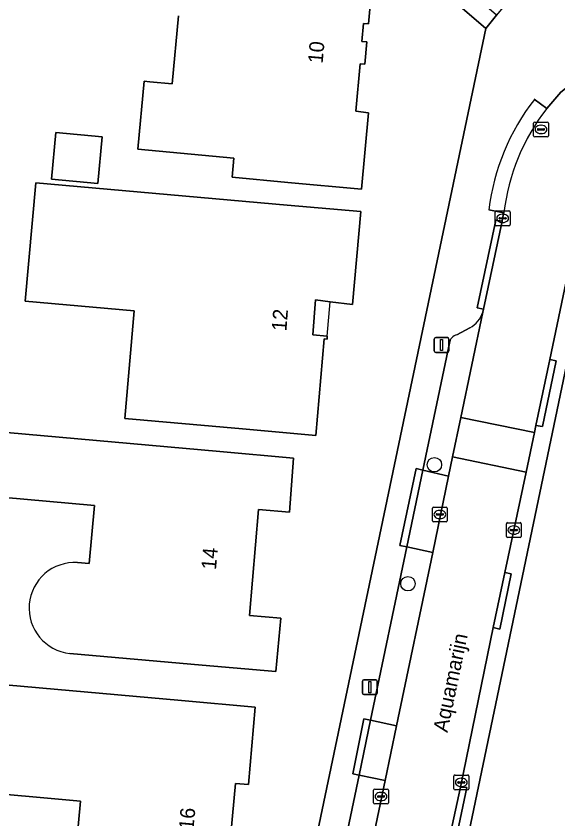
# Model space of a CAD drawing. Extents: x 159626 to 160723, y 388173 to 389416.
# Drawn here: x 159871.8 to 159908.4, y 388559.2 to 388613.5 of the extents above; entities that cross this region are included whole.
import ezdxf

# ---------------------------------------------------------------- set-up
doc = ezdxf.new("R2010")
doc.units = 0
for name, color, linetype in [('IMGEO_Boom', 7, 'Continuous'), ('IMGEO_Erf', 7, 'Continuous'), ('IMGEO_Groenvoorziening', 7, 'Continuous'), ('IMGEO_Kolk', 7, 'Continuous'), ('IMGEO_Lichtmast', 7, 'Continuous'), ('IMGEO_Openbare_ruimte_label', 7, 'Continuous'), ('IMGEO_Pand', 7, 'Continuous'), ('IMGEO_Pand_nummerreeks', 7, 'Continuous'), ('IMGEO_Pand_overbouw', 7, 'Continuous'), ('IMGEO_Parkeervlak_open', 7, 'Continuous'), ('IMGEO_Rijbaan_lokaal_open', 7, 'Continuous'), ('IMGEO_Rioolput', 7, 'Continuous'), ('IMGEO_Voetpad_open', 7, 'Continuous')]:
    doc.layers.add(name, color=color, linetype=linetype)

msp = doc.modelspace()

# ---------------------------------------------------------------- linework, layer by layer
at = {"layer": 'IMGEO_Boom'}
for centre in [(159900.068, 388583.165), (159898.281, 388575.119)]:
    msp.add_circle(centre, 0.489, dxfattribs=at)
at = {"layer": 'IMGEO_Erf'}
for points in [[(159903.537, 388612.665), (159870.877, 388640.759), (159868.257, 388629.83), (159864.584, 388613.795), (159856.856, 388575.073), (159855.899, 388569.574), (159854.79, 388569.739), (159851.654, 388551.438)], [(159895.744, 388614.471), (159895.614, 388612.976), (159895.275, 388613.005), (159895.17, 388611.79), (159895.509, 388611.761), (159895.358, 388610.258), (159895.038, 388610.285), (159894.759, 388607.067), (159895.621, 388606.967), (159895.129, 388601.801), (159890.151, 388602.262), (159886.384, 388602.611), (159886.504, 388603.907), (159880.021, 388604.507), (159880.446, 388609.095), (159880.817, 388609.061), (159882.341, 388608.919), (159882.767, 388613.527)], [(159880.922, 388504.632), (159903.537, 388612.665)], [(159910.917, 388599.067), (159890.615, 388501.836)], [(159875.928, 388576.55), (159876.729, 388576.48), (159877.072, 388580.416), (159870.779, 388580.965), (159870.808, 388581.302), (159864.354, 388581.864), (159864.694, 388585.766), (159871.148, 388585.204), (159871.16, 388585.34), (159885.557, 388584.052), (159890.537, 388583.606), (159890.274, 388579.96), (159888.18, 388580.138), (159887.557, 388572.968), (159889.688, 388572.787), (159889.353, 388569.19), (159884.372, 388569.624), (159875.415, 388570.404)]]:
    msp.add_lwpolyline(points, dxfattribs=at)
for points in [[(159874.169, 388602.469), (159874.461, 388605.625), (159877.59, 388605.335), (159877.297, 388602.179)], [(159872.4, 388594.22), (159873.11, 388602.22), (159890.121, 388600.728), (159895.101, 388600.291), (159894.524, 388594.006), (159893.019, 388594.19), (159892.036, 388594.311), (159891.838, 388591.95), (159892.824, 388591.867), (159892.807, 388591.667), (159892.605, 388591.683), (159892.059, 388585.15), (159887.079, 388585.59), (159879.122, 388586.294), (159879.765, 388593.569)], [(159868.39, 388561.11), (159868.882, 388566.952), (159868.194, 388567.009), (159867.157, 388566.197), (159865.365, 388566.357), (159865.581, 388568.776), (159869.01, 388568.47), (159882.96, 388567.225), (159887.94, 388566.78), (159887.496, 388561.533), (159886.609, 388561.603), (159885.79, 388552.622), (159882.972, 388552.878), (159882.862, 388551.663), (159877.883, 388552.116), (159875.394, 388552.342), (159876.127, 388560.407)]]:
    msp.add_lwpolyline(points, close=True, dxfattribs=at)
msp.add_arc((159875.745, 388573.471), 3.085, 86.5972, 263.8601, dxfattribs=at)
at = {"layer": 'IMGEO_Groenvoorziening'}
msp.add_lwpolyline([(159855.899, 388569.574), (159856.856, 388575.073), (159864.584, 388613.795), (159868.257, 388629.83), (159870.877, 388640.759), (159903.537, 388612.665), (159904.269, 388613.569), (159871.151, 388642.007), (159870.675, 388642.416), (159870.33, 388642.677), (159870.008, 388642.843), (159865.23, 388644.686), (159864.406, 388645.004), (159862.861, 388640.687), (159864.137, 388640.247), (159866.102, 388639.571), (159861.174, 388619.427), (159856.533, 388594.848)], dxfattribs=at)
at = {"layer": 'IMGEO_Kolk'}
for p, q in [((159904.181, 388599.4), (159904.181, 388600.252)), ((159904.256, 388600.326), (159905.108, 388600.326)), ((159904.669, 388600.106), (159904.694, 388600.106)), ((159905.182, 388600.252), (159905.182, 388599.4)), ((159904.44, 388599.82), (159904.44, 388599.832)), ((159904.878, 388599.783), (159904.48, 388599.783)), ((159904.483, 388599.869), (159904.881, 388599.869)), ((159904.692, 388599.546), (159904.667, 388599.546)), ((159904.924, 388599.832), (159904.924, 388599.82)), ((159905.108, 388599.326), (159904.256, 388599.326)), ((159899.938, 388579.376), (159899.938, 388580.228)), ((159900.013, 388580.302), (159900.865, 388580.302)), ((159900.426, 388580.082), (159900.451, 388580.082)), ((159900.939, 388580.228), (159900.939, 388579.376)), ((159900.197, 388579.796), (159900.197, 388579.808)), ((159900.635, 388579.759), (159900.237, 388579.759)), ((159900.24, 388579.845), (159900.638, 388579.845)), ((159900.449, 388579.522), (159900.424, 388579.522)), ((159900.681, 388579.808), (159900.681, 388579.796)), ((159900.865, 388579.302), (159900.013, 388579.302)), ((159904.942, 388578.323), (159904.942, 388579.175)), ((159905.017, 388579.249), (159905.869, 388579.249)), ((159905.43, 388579.029), (159905.455, 388579.029)), ((159905.943, 388579.175), (159905.943, 388578.323)), ((159905.201, 388578.743), (159905.201, 388578.755)), ((159905.639, 388578.706), (159905.241, 388578.706)), ((159905.244, 388578.792), (159905.642, 388578.792)), ((159905.453, 388578.469), (159905.428, 388578.469)), ((159905.685, 388578.755), (159905.685, 388578.743)), ((159905.869, 388578.249), (159905.017, 388578.249)), ((159901.388, 388561.26), (159901.388, 388562.112)), ((159901.463, 388562.186), (159902.315, 388562.186)), ((159902.389, 388562.112), (159902.389, 388561.26)), ((159901.647, 388561.68), (159901.647, 388561.692)), ((159902.085, 388561.643), (159901.687, 388561.643)), ((159901.69, 388561.729), (159902.088, 388561.729)), ((159901.876, 388561.966), (159901.901, 388561.966)), ((159902.131, 388561.692), (159902.131, 388561.68)), ((159895.955, 388560.307), (159895.955, 388561.159)), ((159896.03, 388561.233), (159896.882, 388561.233)), ((159896.443, 388561.013), (159896.468, 388561.013)), ((159896.956, 388561.159), (159896.956, 388560.307)), ((159902.315, 388561.186), (159901.463, 388561.186)), ((159901.899, 388561.406), (159901.874, 388561.406)), ((159896.214, 388560.727), (159896.214, 388560.739)), ((159896.652, 388560.69), (159896.254, 388560.69)), ((159896.257, 388560.776), (159896.655, 388560.776)), ((159896.466, 388560.453), (159896.441, 388560.453)), ((159896.698, 388560.739), (159896.698, 388560.727)), ((159896.882, 388560.233), (159896.03, 388560.233))]:
    msp.add_line(p, q, dxfattribs=at)
for points in [[(159904.181, 388599.4), (159904.181, 388600.252)], [(159904.256, 388600.326), (159905.108, 388600.326)], [(159905.182, 388600.252), (159905.182, 388599.4)], [(159905.108, 388599.326), (159904.256, 388599.326)], [(159899.938, 388579.376), (159899.938, 388580.228)], [(159900.013, 388580.302), (159900.865, 388580.302)], [(159900.939, 388580.228), (159900.939, 388579.376)], [(159900.865, 388579.302), (159900.013, 388579.302)], [(159904.942, 388578.323), (159904.942, 388579.175)], [(159905.017, 388579.249), (159905.869, 388579.249)], [(159905.943, 388579.175), (159905.943, 388578.323)], [(159905.869, 388578.249), (159905.017, 388578.249)], [(159901.388, 388561.26), (159901.388, 388562.112)], [(159901.463, 388562.186), (159902.315, 388562.186)], [(159902.389, 388562.112), (159902.389, 388561.26)], [(159895.955, 388560.307), (159895.955, 388561.159)], [(159896.03, 388561.233), (159896.882, 388561.233)], [(159896.956, 388561.159), (159896.956, 388560.307)], [(159902.315, 388561.186), (159901.463, 388561.186)], [(159896.882, 388560.233), (159896.03, 388560.233)]]:
    msp.add_lwpolyline(points, dxfattribs=at)
for centre, radius, start, end in [((159904.258, 388600.25), 0.0765, 91.552, 178.448), ((159904.258, 388600.25), 0.0765, 91.552, 178.448), ((159905.106, 388600.25), 0.0765, 1.552, 88.448), ((159905.106, 388600.25), 0.0765, 1.552, 88.448), ((159904.48, 388599.829), 0.0403, 85.8775, 175.7526), ((159904.477, 388599.819), 0.0366, 178.938, 274.7102), ((159904.881, 388599.826), 0.043, 264.8664, 352.4533), ((159904.885, 388599.831), 0.0386, 1.7309, 96.639), ((159904.258, 388599.402), 0.0765, 181.552, 268.448), ((159904.258, 388599.402), 0.0765, 181.552, 268.448), ((159905.106, 388599.402), 0.0765, 271.552, 358.448), ((159905.106, 388599.402), 0.0765, 271.552, 358.448), ((159900.015, 388580.226), 0.0765, 91.552, 178.448), ((159900.015, 388580.226), 0.0765, 91.552, 178.448), ((159900.863, 388580.226), 0.0765, 1.552, 88.448), ((159900.863, 388580.226), 0.0765, 1.552, 88.448), ((159900.015, 388579.378), 0.0765, 181.552, 268.448), ((159900.015, 388579.378), 0.0765, 181.552, 268.448), ((159900.237, 388579.805), 0.0403, 85.8775, 175.7526), ((159900.234, 388579.795), 0.0366, 178.938, 274.7102), ((159900.638, 388579.802), 0.043, 264.8664, 352.4533), ((159900.642, 388579.807), 0.0386, 1.7309, 96.639), ((159900.863, 388579.378), 0.0765, 271.552, 358.448), ((159900.863, 388579.378), 0.0765, 271.552, 358.448), ((159905.019, 388579.173), 0.0765, 91.552, 178.448), ((159905.019, 388579.173), 0.0765, 91.552, 178.448), ((159905.867, 388579.173), 0.0765, 1.552, 88.448), ((159905.867, 388579.173), 0.0765, 1.552, 88.448), ((159905.019, 388578.325), 0.0765, 181.552, 268.448), ((159905.019, 388578.325), 0.0765, 181.552, 268.448), ((159905.241, 388578.752), 0.0403, 85.8775, 175.7526), ((159905.238, 388578.742), 0.0366, 178.938, 274.7102), ((159905.642, 388578.749), 0.043, 264.8664, 352.4533), ((159905.646, 388578.754), 0.0386, 1.7309, 96.639), ((159905.867, 388578.325), 0.0765, 271.552, 358.448), ((159905.867, 388578.325), 0.0765, 271.552, 358.448), ((159901.465, 388562.11), 0.0765, 91.552, 178.448), ((159901.465, 388562.11), 0.0765, 91.552, 178.448), ((159902.313, 388562.11), 0.0765, 1.552, 88.448), ((159902.313, 388562.11), 0.0765, 1.552, 88.448), ((159901.687, 388561.689), 0.0403, 85.8775, 175.7526), ((159901.684, 388561.679), 0.0366, 178.938, 274.7102), ((159902.088, 388561.686), 0.043, 264.8664, 352.4533), ((159902.092, 388561.691), 0.0386, 1.7309, 96.639), ((159896.032, 388561.157), 0.0765, 91.552, 178.448), ((159896.032, 388561.157), 0.0765, 91.552, 178.448), ((159896.88, 388561.157), 0.0765, 1.552, 88.448), ((159896.88, 388561.157), 0.0765, 1.552, 88.448), ((159901.465, 388561.262), 0.0765, 181.552, 268.448), ((159901.465, 388561.262), 0.0765, 181.552, 268.448), ((159902.313, 388561.262), 0.0765, 271.552, 358.448), ((159902.313, 388561.262), 0.0765, 271.552, 358.448), ((159896.254, 388560.736), 0.0403, 85.8775, 175.7526), ((159896.251, 388560.726), 0.0366, 178.938, 274.7102), ((159896.655, 388560.733), 0.043, 264.8664, 352.4533), ((159896.659, 388560.738), 0.0386, 1.7309, 96.639), ((159896.032, 388560.309), 0.0765, 181.552, 268.448), ((159896.032, 388560.309), 0.0765, 181.552, 268.448), ((159896.88, 388560.309), 0.0765, 271.552, 358.448), ((159896.88, 388560.309), 0.0765, 271.552, 358.448)]:
    msp.add_arc(centre, radius, start, end, dxfattribs=at)
for centre, major_axis, ratio, start_param, end_param in [((159904.668, 388599.826), (-0.387, 0.002), 0.722429, 4.712389, 7.853982), ((159904.693, 388599.826), (-0.39, 0.002), 0.717154, 1.570796, 4.712389), ((159900.425, 388579.802), (-0.387, 0.002), 0.722429, 4.712389, 7.853982), ((159900.45, 388579.802), (-0.39, 0.002), 0.717154, 1.570796, 4.712389), ((159905.429, 388578.749), (-0.387, 0.002), 0.722429, 4.712389, 7.853982), ((159905.454, 388578.749), (-0.39, 0.002), 0.717154, 1.570796, 4.712389), ((159901.875, 388561.686), (-0.387, 0.002), 0.722429, 4.712389, 7.853982), ((159901.9, 388561.686), (-0.39, 0.002), 0.717154, 1.570796, 4.712389), ((159896.442, 388560.733), (-0.387, 0.002), 0.722429, 4.712389, 7.853982), ((159896.467, 388560.733), (-0.39, 0.002), 0.717154, 1.570796, 4.712389)]:
    msp.add_ellipse(centre, major_axis=major_axis, ratio=ratio, start_param=start_param, end_param=end_param, dxfattribs=at)
at = {"layer": 'IMGEO_Lichtmast'}
for p, q in [((159900.054, 388590.864), (159900.054, 388591.664)), ((159900.054, 388591.664), (159900.054, 388590.864)), ((159900.154, 388591.764), (159900.944, 388591.764)), ((159900.944, 388591.764), (159900.154, 388591.764)), ((159901.044, 388591.664), (159901.044, 388590.864)), ((159901.044, 388590.864), (159901.044, 388591.664)), ((159900.944, 388590.764), (159900.154, 388590.764)), ((159900.154, 388590.764), (159900.944, 388590.764)), ((159895.206, 388567.725), (159895.206, 388568.525)), ((159895.206, 388568.525), (159895.206, 388567.725)), ((159895.306, 388568.625), (159896.096, 388568.625)), ((159896.096, 388568.625), (159895.306, 388568.625)), ((159896.196, 388568.525), (159896.196, 388567.725)), ((159896.196, 388567.725), (159896.196, 388568.525)), ((159896.096, 388567.625), (159895.306, 388567.625)), ((159895.306, 388567.625), (159896.096, 388567.625))]:
    msp.add_line(p, q, dxfattribs=at)
for points in [[(159900.474, 388591.639), (159900.624, 388591.639), (159900.624, 388590.889), (159900.474, 388590.889), (159900.474, 388591.639)], [(159895.626, 388568.5), (159895.776, 388568.5), (159895.776, 388567.75), (159895.626, 388567.75), (159895.626, 388568.5)]]:
    msp.add_lwpolyline(points, dxfattribs=at)
for centre, start, end in [((159900.154, 388591.664), 90, 180), ((159900.154, 388591.664), 90, 180), ((159900.944, 388591.664), 0, 90), ((159900.944, 388591.664), 360, 90), ((159900.154, 388590.864), 180, 270), ((159900.154, 388590.864), 180, 270), ((159900.944, 388590.864), 270, 0), ((159900.944, 388590.864), 270, 0), ((159895.306, 388568.525), 90, 180), ((159895.306, 388568.525), 90, 180), ((159896.096, 388568.525), 0, 90), ((159896.096, 388568.525), 360, 90), ((159895.306, 388567.725), 180, 270), ((159895.306, 388567.725), 180, 270), ((159896.096, 388567.725), 270, 0), ((159896.096, 388567.725), 270, 0)]:
    msp.add_arc(centre, 0.1, start, end, dxfattribs=at)
at = {"layer": 'IMGEO_Pand'}
for points in [[(159882.767, 388613.527), (159882.341, 388608.919), (159880.817, 388609.061), (159880.446, 388609.095), (159880.021, 388604.507), (159886.504, 388603.907), (159886.384, 388602.611), (159890.151, 388602.262), (159895.129, 388601.801), (159895.621, 388606.967), (159894.759, 388607.067), (159895.038, 388610.285), (159895.358, 388610.258), (159895.509, 388611.761), (159895.17, 388611.79), (159895.275, 388613.005), (159895.614, 388612.976), (159895.744, 388614.471)], [(159888.18, 388580.138), (159890.274, 388579.96), (159890.537, 388583.606), (159885.557, 388584.052), (159871.16, 388585.34), (159871.148, 388585.204), (159870.808, 388581.302), (159870.779, 388580.965), (159877.072, 388580.416), (159876.729, 388576.48), (159875.928, 388576.55)], [(159875.415, 388570.404), (159884.372, 388569.624), (159889.353, 388569.19), (159889.688, 388572.787), (159887.557, 388572.968), (159888.18, 388580.138)]]:
    msp.add_lwpolyline(points, dxfattribs=at)
for points in [[(159877.59, 388605.335), (159874.461, 388605.625), (159874.169, 388602.469), (159877.297, 388602.179)], [(159893.019, 388594.19), (159894.524, 388594.006), (159895.101, 388600.291), (159890.121, 388600.728), (159873.11, 388602.22), (159872.4, 388594.22), (159879.765, 388593.569), (159879.122, 388586.294), (159887.079, 388585.59), (159892.059, 388585.15), (159892.605, 388591.683), (159892.807, 388591.667), (159892.824, 388591.867), (159891.838, 388591.95), (159892.036, 388594.311)], [(159869.01, 388568.47), (159865.581, 388568.776), (159865.365, 388566.357), (159867.157, 388566.197), (159868.194, 388567.009), (159868.882, 388566.952), (159868.39, 388561.11), (159876.127, 388560.407), (159875.394, 388552.342), (159877.883, 388552.116), (159882.862, 388551.663), (159882.972, 388552.878), (159885.79, 388552.622), (159886.609, 388561.603), (159887.496, 388561.533), (159887.94, 388566.78), (159882.96, 388567.225)]]:
    msp.add_lwpolyline(points, close=True, dxfattribs=at)
msp.add_arc((159875.745, 388573.471), 3.085, 86.5972, 263.8601, dxfattribs=at)
at = {"layer": 'IMGEO_Pand_overbouw'}
msp.add_lwpolyline([(159893.019, 388594.19), (159892.036, 388594.311), (159891.838, 388591.95), (159892.824, 388591.867)], close=True, dxfattribs=at)
at = {"layer": 'IMGEO_Parkeervlak_open'}
for points in [[(159901.09, 388591.384), (159899.283, 388582.799), (159901.032, 388582.402), (159901.302, 388583.693), (159901.859, 388586.36), (159903.349, 388593.491)], [(159902.475, 388592.429), (159901.594, 388591.959)]]:
    msp.add_lwpolyline(points, dxfattribs=at)
for points in [[(159901.032, 388582.402), (159899.283, 388582.799), (159898.198, 388577.61), (159899.954, 388577.243)], [(159899.954, 388577.243), (159898.198, 388577.61), (159895.745, 388565.885), (159897.504, 388565.517)], [(159897.504, 388565.517), (159895.745, 388565.885), (159894.97, 388562.181), (159896.73, 388561.813)], [(159896.73, 388561.813), (159894.97, 388562.181), (159889.959, 388538.221), (159891.723, 388537.852)]]:
    msp.add_lwpolyline(points, close=True, dxfattribs=at)
for centre, radius, start, end in [((159901.541, 388594.088), 1.904, 299.3707, 341.7222), ((159901.724, 388591.337), 0.635, 101.7721, 175.7573)]:
    msp.add_arc(centre, radius, start, end, dxfattribs=at)
at = {"layer": 'IMGEO_Rijbaan_lokaal_open'}
for points in [[(159913.358, 388605.815), (159914.07, 388606.423), (159932.598, 388621.187), (159933.737, 388622.071), (159930.674, 388625.944), (159929.504, 388625.028), (159924.843, 388621.328), (159908.628, 388608.359), (159907.664, 388607.259)], [(159904.765, 388600.195), (159904.679, 388599.826), (159904.661, 388599.629), (159903.389, 388593.676), (159903.349, 388593.491), (159901.859, 388586.36), (159906.837, 388585.341), (159906.939, 388585.824), (159907.864, 388590.284), (159909.761, 388599.318)]]:
    msp.add_lwpolyline(points, dxfattribs=at)
for points in [[(159901.859, 388586.36), (159901.302, 388583.693), (159906.268, 388582.656), (159906.837, 388585.341)], [(159900.706, 388556.171), (159901.827, 388561.363), (159904.043, 388572.152), (159904.831, 388575.878), (159906.268, 388582.656), (159901.302, 388583.693), (159901.032, 388582.402), (159899.954, 388577.243), (159897.504, 388565.517), (159896.73, 388561.813), (159891.723, 388537.852), (159891.115, 388534.944), (159890.558, 388532.274), (159889.31, 388526.304), (159887.996, 388520.015), (159892.92, 388519.028), (159894.104, 388524.658), (159895.037, 388529.114), (159897.401, 388540.306), (159898.454, 388545.528)]]:
    msp.add_lwpolyline(points, close=True, dxfattribs=at)
msp.add_arc((159918.924, 388598.511), 14.259, 142.1568, 173.2176, dxfattribs=at)
at = {"layer": 'IMGEO_Rioolput'}
for p, q in [((159906.777, 388605.414), (159906.777, 388606.266)), ((159906.852, 388606.34), (159907.704, 388606.34)), ((159907.265, 388606.12), (159907.29, 388606.12)), ((159907.778, 388606.266), (159907.778, 388605.414)), ((159907.036, 388605.834), (159907.036, 388605.846)), ((159907.474, 388605.797), (159907.076, 388605.797)), ((159907.079, 388605.883), (159907.477, 388605.883)), ((159907.288, 388605.56), (159907.263, 388605.56)), ((159907.52, 388605.846), (159907.52, 388605.834)), ((159907.704, 388605.34), (159906.852, 388605.34))]:
    msp.add_line(p, q, dxfattribs=at)
for points in [[(159906.777, 388605.414), (159906.777, 388606.266)], [(159906.852, 388606.34), (159907.704, 388606.34)], [(159907.778, 388606.266), (159907.778, 388605.414)], [(159907.704, 388605.34), (159906.852, 388605.34)]]:
    msp.add_lwpolyline(points, dxfattribs=at)
for centre, radius, start, end in [((159906.854, 388606.264), 0.0765, 91.552, 178.448), ((159906.854, 388606.264), 0.0765, 91.552, 178.448), ((159907.702, 388606.264), 0.0765, 1.552, 88.448), ((159907.702, 388606.264), 0.0765, 1.552, 88.448), ((159907.076, 388605.843), 0.0403, 85.8775, 175.7526), ((159907.073, 388605.833), 0.0366, 178.938, 274.7102), ((159907.477, 388605.84), 0.043, 264.8664, 352.4533), ((159907.481, 388605.845), 0.0386, 1.7309, 96.639), ((159906.854, 388605.416), 0.0765, 181.552, 268.448), ((159906.854, 388605.416), 0.0765, 181.552, 268.448), ((159907.702, 388605.416), 0.0765, 271.552, 358.448), ((159907.702, 388605.416), 0.0765, 271.552, 358.448)]:
    msp.add_arc(centre, radius, start, end, dxfattribs=at)
for centre, major_axis, ratio, start_param, end_param in [((159907.264, 388605.84), (-0.387, 0.002), 0.722429, 4.712389, 7.853982), ((159907.289, 388605.84), (-0.39, 0.002), 0.717154, 1.570796, 4.712389)]:
    msp.add_ellipse(centre, major_axis=major_axis, ratio=ratio, start_param=start_param, end_param=end_param, dxfattribs=at)
at = {"layer": 'IMGEO_Voetpad_open'}
for points in [[(159933.062, 388629.465), (159930.846, 388627.835), (159913.35, 388614.019), (159906.097, 388615.825), (159905.322, 388614.867), (159904.269, 388613.569), (159903.537, 388612.665), (159880.922, 388504.632)], [(159906.826, 388607.875), (159907.664, 388607.259), (159908.628, 388608.359), (159924.843, 388621.328), (159929.504, 388625.028), (159930.674, 388625.944), (159932.015, 388627.053)], [(159907.664, 388607.259), (159906.826, 388607.875)], [(159903.349, 388593.491), (159903.389, 388593.676), (159902.95, 388593.771), (159904.219, 388599.707), (159904.661, 388599.629), (159904.679, 388599.826), (159904.765, 388600.195), (159903.743, 388600.405)], [(159903.743, 388600.405), (159904.765, 388600.195)], [(159890.615, 388501.836), (159910.917, 388599.067), (159909.761, 388599.318), (159907.864, 388590.284), (159908.296, 388590.183), (159907.389, 388585.741), (159906.939, 388585.824), (159906.837, 388585.341), (159906.268, 388582.656), (159904.831, 388575.878), (159905.256, 388575.793), (159904.485, 388572.054), (159904.043, 388572.152), (159901.827, 388561.363), (159902.255, 388561.334), (159901.147, 388556.088)], [(159901.594, 388591.959), (159902.475, 388592.429)], [(159894.97, 388562.181), (159894.546, 388562.276), (159895.298, 388565.98), (159895.745, 388565.885), (159898.198, 388577.61), (159897.738, 388577.701), (159898.835, 388582.901), (159899.283, 388582.799), (159901.09, 388591.384)], [(159882.83, 388504.14), (159884.253, 388510.943), (159883.834, 388511.037), (159885.037, 388516.964), (159885.496, 388516.887), (159887.543, 388526.673), (159887.111, 388526.782), (159888.347, 388532.725), (159888.792, 388532.643), (159889.351, 388535.313), (159889.959, 388538.221), (159894.97, 388562.181)]]:
    msp.add_lwpolyline(points, dxfattribs=at)
for points in [[(159904.661, 388599.629), (159904.219, 388599.707), (159902.95, 388593.771), (159903.389, 388593.676)], [(159906.939, 388585.824), (159907.389, 388585.741), (159908.296, 388590.183), (159907.864, 388590.284)], [(159899.283, 388582.799), (159898.835, 388582.901), (159897.738, 388577.701), (159898.198, 388577.61)], [(159904.043, 388572.152), (159904.485, 388572.054), (159905.256, 388575.793), (159904.831, 388575.878)], [(159894.97, 388562.181), (159895.745, 388565.885), (159895.298, 388565.98), (159894.546, 388562.276)], [(159901.827, 388561.363), (159900.706, 388556.171), (159901.147, 388556.088), (159902.255, 388561.334)]]:
    msp.add_lwpolyline(points, close=True, dxfattribs=at)
for centre, radius, start, end in [((159918.918, 388598.513), 15.292, 142.2524, 172.894), ((159918.918, 388598.513), 15.292, 142.2524, 172.894), ((159918.924, 388598.511), 14.259, 142.1568, 173.2176), ((159901.541, 388594.088), 1.904, 299.3707, 341.7222), ((159901.724, 388591.337), 0.635, 101.7721, 175.7573)]:
    msp.add_arc(centre, radius, start, end, dxfattribs=at)

# ---------------------------------------------------------------- texts
at = {"layer": 'IMGEO_Openbare_ruimte_label'}
msp.add_text('Aquamarijn', height=1, rotation=78.2294, dxfattribs=at).set_placement((159900.949, 388565.022))
at = {"layer": 'IMGEO_Pand_nummerreeks'}
for s, rotation, p in [('10', 85.0329, (159892.508, 388610.273)), ('12', 85.7179, (159890.058, 388592.173)), ('14', 85.0327, (159885.294, 388576.039)), ('16', 84.7895, (159883.771, 388558.45))]:
    msp.add_text(s, height=1, rotation=rotation, dxfattribs=at).set_placement(p)

doc.saveas('drawing.dxf')
